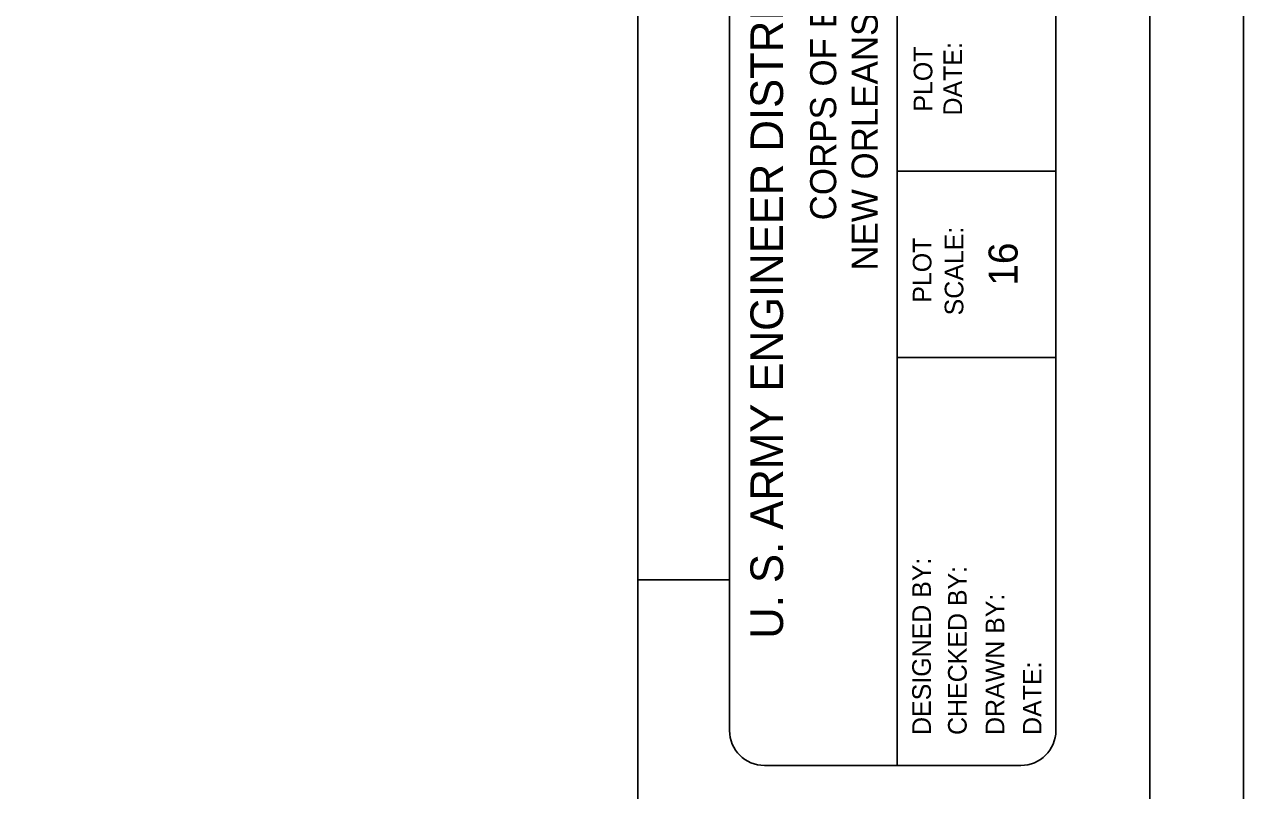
# Model space of a CAD drawing. Extents: x 22369.6 to 22428.3, y 22369.6 to 22415.
# Drawn here: x 22419.56 to 22428.29, y 22379.78 to 22385.26 of the extents above; entities that cross this region are included whole.
import ezdxf

# ---------------------------------------------------------------- set-up
doc = ezdxf.new("R2010")
doc.units = 0
for name, color, linetype in [('Level 1', 7, 'Continuous'), ('Level 10', 7, 'Continuous'), ('Level 2', 7, 'Continuous'), ('Level 7', 7, 'Continuous'), ('Level 9', 7, 'Continuous')]:
    doc.layers.add(name, color=color, linetype=linetype)

msp = doc.modelspace()

# ---------------------------------------------------------------- linework, layer by layer
at = {"layer": 'Level 1'}
msp.add_line((22425.8085, 22391.1253), (22425.8085, 22379.9573), dxfattribs=at)
msp.add_lwpolyline([(22369.6213, 22414.9653), (22428.2885, 22414.9653), (22428.2885, 22369.6213), (22369.6213, 22369.6213)], close=True, dxfattribs=at)
for points in [[(22424.6085, 22380.2073), (22424.6085, 22390.8753)], [(22426.9445, 22380.2073), (22426.9445, 22390.8753)], [(22424.8585, 22379.9573), (22426.6945, 22379.9573)]]:
    msp.add_lwpolyline(points, dxfattribs=at)
for centre, start, end in [((22424.8585, 22380.2073), 180, 270), ((22426.6945, 22380.2073), 270, 0)]:
    msp.add_arc(centre, 0.25, start, end, dxfattribs=at)
at = {"layer": 'Level 10'}
msp.add_line((22423.9525, 22381.2853), (22424.6085, 22381.2853), dxfattribs=at)
at = {"layer": 'Level 2'}
for p, q in [((22426.9445, 22384.208), (22425.8085, 22384.208)), ((22426.9445, 22382.8746), (22425.8085, 22382.8746))]:
    msp.add_line(p, q, dxfattribs=at)
at = {"layer": 'Level 9'}
msp.add_line((22427.6165, 22370.2933), (22427.6165, 22414.2933), dxfattribs=at)
msp.add_lwpolyline([(22423.9525, 22370.2933), (22423.9525, 22414.2933)], dxfattribs=at)

# ---------------------------------------------------------------- texts
at = {"layer": 'Level 1'}
for s, height, p in [('U. S. ARMY ENGINEER DISTRICT, NEW ORLEANS', 0.233332, (22424.9915, 22380.8633)), ('PLOT', 0.13334, (22426.0601, 22384.6335)), ('DATE:', 0.13334, (22426.273, 22384.6056)), ('PLOT', 0.13334, (22426.0536, 22383.2668)), ('SCALE:', 0.13334, (22426.2821, 22383.1763)), ('DESIGNED BY:', 0.133343, (22426.0498, 22380.1756)), ('CHECKED BY:', 0.133343, (22426.3058, 22380.1756)), ('DRAWN BY:', 0.13334, (22426.575, 22380.1756)), ('DATE:', 0.13334, (22426.8415, 22380.1756))]:
    msp.add_text(s, height=height, rotation=90, dxfattribs=at).set_placement(p)
at = {"layer": 'Level 7'}
for s, height, p in [('NEW ORLEANS, LOUISIANA', 0.186666, (22425.6693, 22383.4965)), ('CORPS OF ENGINEERS', 0.186666, (22425.372, 22383.8561)), ('16', 0.208, (22426.6706, 22383.388))]:
    msp.add_text(s, height=height, rotation=90, dxfattribs=at).set_placement(p)

doc.saveas('drawing.dxf')
